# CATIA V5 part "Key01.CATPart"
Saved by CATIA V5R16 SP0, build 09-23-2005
Part number: Key01
Bounding box of the stored display mesh (mm): x -4 to 11, y -4 to 4, z 0 to 7.3
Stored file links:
  C:\V5_education\CATIA Data\ASD\Power Transmission Gear Assembly\Assembly Data\Key01.CATPart
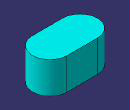
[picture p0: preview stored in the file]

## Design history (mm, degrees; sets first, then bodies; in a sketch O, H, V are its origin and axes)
Set1 "Reference Data"
  Point1 "Center Point": (0, 0, 0)
Body1 (main body)
  Sketch1 on xy-plane, origin (0, 0, 0), H (1, 0, 0), V (0, 1, 0)
    construction line L1 (0, 0) -> (7, 0)
    line L2 (0, 4) -> (7, 4)
    line L3 (7, -4) -> (0, -4)
    arc A1 centre (7, 0) radius 4 from (7, 4) to (7, -4) cw
    arc A2 centre (0, 0) radius 4 from (0, -4) to (0, 4) cw
    distance L1 L2 = 4
    distance A2 A1 = 15
    horizontal: L1 H
    tangency: A1 L2, A2 L2, A1 L3, A2 L3
  Pad1: profile Sketch1, direction (0, 0, 1), length 7.3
